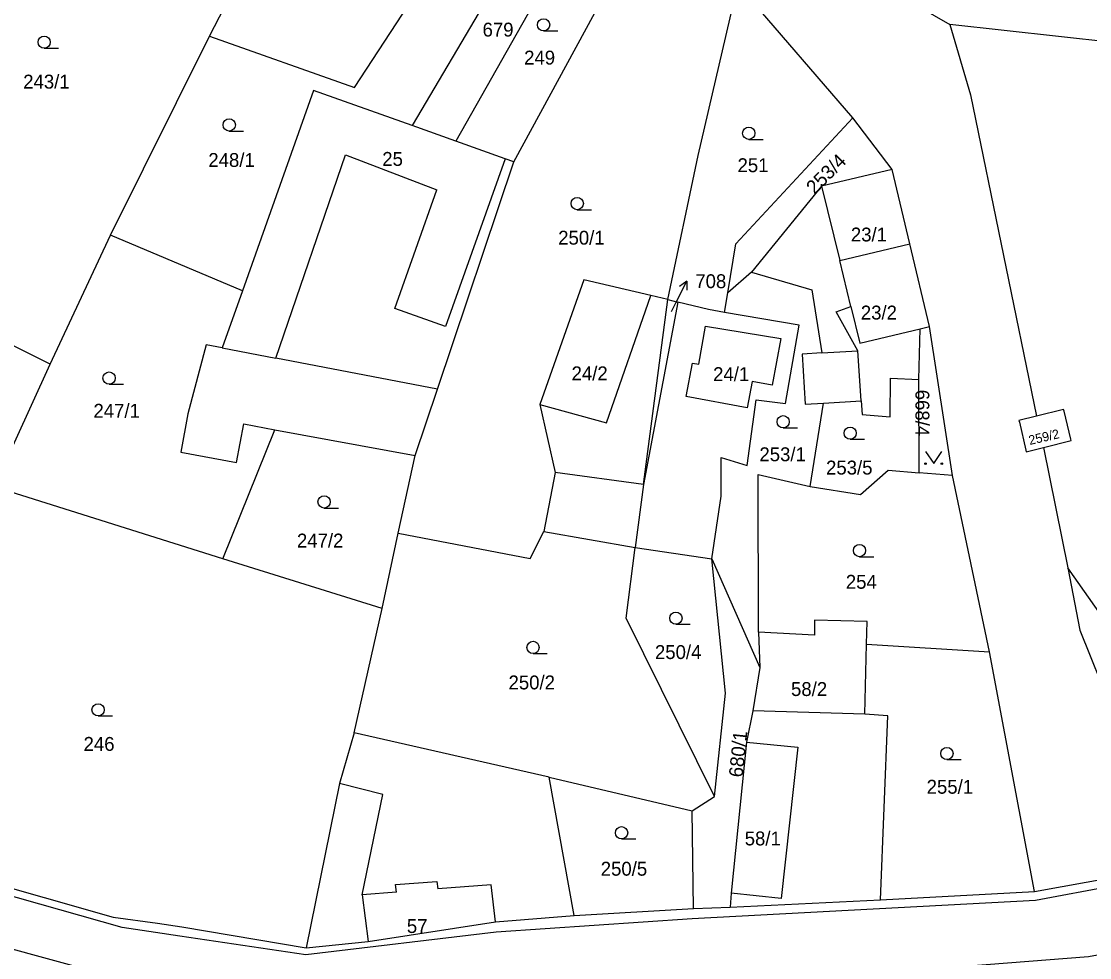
# Model space of a CAD drawing. Extents: x -747333 to -743907, y -1134120 to -1130051.
# Drawn here: x -746462.8 to -746332, y -1132327 to -1132212.3 of the extents above; entities that cross this region are included whole.
import ezdxf

# ---------------------------------------------------------------- set-up
doc = ezdxf.new("R2010")
doc.units = 0
for name, color, linetype in [('Hranice parcel', 7, 'Continuous'), ('Parcelní čísla', 7, 'Continuous'), ('Pop  PČ popisy', 7, 'Continuous'), ('Vnitřní kresba', 7, 'Continuous'), ('Značky kultur', 7, 'Continuous')]:
    doc.layers.add(name, color=color, linetype=linetype)

msp = doc.modelspace()

# ---------------------------------------------------------------- linework, layer by layer
at = {"layer": 'Hranice parcel'}
for p, q in [((-746385.31, -1132191.74), (-746349.14, -1132212.69)), ((-746439.77, -1132214.12), (-746430.73, -1132196.48)), ((-746398.19, -1132196.61), (-746414.98, -1132225.06)), ((-746394.06, -1132199.47), (-746409.61, -1132226.97)), ((-746402.53, -1132229.49), (-746387.86, -1132202.51)), ((-746451.89, -1132238.47), (-746439.77, -1132214.12)), ((-746356.19, -1132230.43), (-746361.01, -1132224.1)), ((-746409.61, -1132226.97), (-746414.98, -1132225.06)), ((-746354.02, -1132239.56), (-746356.19, -1132230.43)), ((-746459.31, -1132254.28), (-746451.89, -1132238.47)), ((-746435.76, -1132245.3), (-746451.89, -1132238.47)), ((-746351.62, -1132249.69), (-746354.02, -1132239.56)), ((-746459.31, -1132254.28), (-746488.24, -1132239.95)), ((-746373.4, -1132243.01), (-746376.31, -1132245.54)), ((-746386.66, -1132269.02), (-746383.65, -1132246.38)), ((-746383.65, -1132246.38), (-746382.45, -1132246.69)), ((-746376.71, -1132247.95), (-746376.31, -1132245.54)), ((-746382.45, -1132246.69), (-746386.66, -1132269.02)), ((-746367.58, -1132249.53), (-746376.71, -1132247.95)), ((-746369.24, -1132259.11), (-746367.58, -1132249.53)), ((-746348.82, -1132267.93), (-746351.62, -1132249.69)), ((-746466.16, -1132269.31), (-746459.31, -1132254.28)), ((-746352.9, -1132267.59), (-746352.94, -1132256.15)), ((-746366.22, -1132269.26), (-746364.59, -1132259.06)), ((-746364.59, -1132259.06), (-746360, -1132258.78)), ((-746435.59, -1132261.62), (-746431.77, -1132262.32)), ((-746438.16, -1132278.12), (-746431.77, -1132262.32)), ((-746431.77, -1132262.32), (-746414.59, -1132265.47)), ((-746337.67, -1132264.5), (-746334.69, -1132279.22)), ((-746416.68, -1132275.01), (-746414.59, -1132265.47)), ((-746348.82, -1132267.93), (-746352.9, -1132267.59)), ((-746344.28, -1132289.52), (-746348.82, -1132267.93)), ((-746438.16, -1132278.12), (-746466.16, -1132269.31)), ((-746386.66, -1132269.02), (-746387.66, -1132276.75)), ((-746418.66, -1132284.23), (-746416.68, -1132275.01)), ((-746398.85, -1132274.79), (-746387.66, -1132276.75)), ((-746387.66, -1132276.75), (-746378.28, -1132278.15)), ((-746418.66, -1132284.23), (-746438.16, -1132278.12)), ((-746378.28, -1132278.15), (-746372.39, -1132291.44)), ((-746422.09, -1132299.47), (-746418.66, -1132284.23)), ((-746372.56, -1132287.12), (-746372.39, -1132291.44)), ((-746359.56, -1132297.17), (-746359.35, -1132288.57)), ((-746359.35, -1132288.57), (-746344.28, -1132289.52)), ((-746338.75, -1132318.87), (-746344.28, -1132289.52)), ((-746372.39, -1132291.44), (-746373.25, -1132296.77)), ((-746359.56, -1132297.17), (-746373.25, -1132296.77)), ((-746398.2, -1132304.9), (-746422.09, -1132299.47)), ((-746398.2, -1132304.9), (-746380.7, -1132309.01)), ((-746395.13, -1132321.84), (-746398.2, -1132304.9)), ((-746380.7, -1132309.01), (-746377.93, -1132307.24)), ((-746380.5, -1132320.99), (-746380.7, -1132309.01)), ((-746338.75, -1132318.87), (-746321.59, -1132315.77)), ((-746357.62, -1132319.89), (-746338.75, -1132318.87)), ((-746395.13, -1132321.84), (-746380.5, -1132320.99)), ((-746380.5, -1132320.99), (-746376.02, -1132320.81)), ((-746376.02, -1132320.81), (-746357.62, -1132319.89))]:
    msp.add_line(p, q, dxfattribs=at)
for points in [[(-746439.77, -1132214.12), (-746422.02, -1132220.4), (-746413.23, -1132206.88), (-746403.66, -1132192.14)], [(-746383.65, -1132246.38), (-746379.95, -1132228.73), (-746375.2, -1132208.32)], [(-746361.01, -1132224.1), (-746374.1, -1132208.89), (-746375.2, -1132208.32)], [(-746308.1, -1132223.28), (-746309.97, -1132217.3), (-746329.17, -1132214.87), (-746349.14, -1132212.69)], [(-746349.14, -1132212.69), (-746346.6, -1132221.28), (-746338.5, -1132260.67)], [(-746414.98, -1132225.06), (-746427.06, -1132220.77), (-746435.76, -1132245.3)], [(-746376.31, -1132245.54), (-746375.33, -1132239.55), (-746361.01, -1132224.1)], [(-746402.53, -1132229.49), (-746403.57, -1132229.12), (-746409.61, -1132226.97)], [(-746414.59, -1132265.47), (-746411.87, -1132257.36), (-746402.53, -1132229.49)], [(-746356.19, -1132230.43), (-746364.83, -1132232.5), (-746373.4, -1132243.01)], [(-746361.26, -1132247.22), (-746362.62, -1132241.61), (-746354.02, -1132239.56)], [(-746373.4, -1132243.01), (-746366.05, -1132245.19), (-746364.79, -1132252.91), (-746367.22, -1132253.06)], [(-746383.65, -1132246.38), (-746385.74, -1132245.89), (-746393.93, -1132243.96), (-746399.35, -1132259.24), (-746397.47, -1132267.55), (-746398.85, -1132274.79)], [(-746435.76, -1132245.3), (-746438.24, -1132252.29), (-746440.19, -1132251.91), (-746442.43, -1132260.37), (-746443.3, -1132265.09)], [(-746376.71, -1132247.95), (-746378.69, -1132247.61), (-746382.45, -1132246.69)], [(-746360, -1132258.78), (-746360.38, -1132252.64), (-746363.05, -1132247.88), (-746361.26, -1132247.22)], [(-746352.94, -1132256.15), (-746352.78, -1132249.96), (-746351.62, -1132249.69)], [(-746367.22, -1132253.06), (-746366.84, -1132259.2), (-746364.59, -1132259.06)], [(-746360, -1132258.78), (-746359.86, -1132260.47), (-746356.42, -1132260.75), (-746356.38, -1132256.01), (-746352.94, -1132256.15)], [(-746378.28, -1132278.15), (-746377.13, -1132270.44), (-746377.15, -1132265.72), (-746373.96, -1132266.7), (-746372.85, -1132258.64), (-746369.24, -1132259.11)], [(-746338.5, -1132260.67), (-746340.67, -1132261.21), (-746340.62, -1132261.4), (-746339.84, -1132264.84), (-746339.8, -1132265.03), (-746337.67, -1132264.5)], [(-746337.67, -1132264.5), (-746334.26, -1132263.66), (-746334.31, -1132263.47), (-746335.15, -1132260.05), (-746335.2, -1132259.86), (-746338.5, -1132260.67)], [(-746443.3, -1132265.09), (-746436.46, -1132266.34), (-746435.59, -1132261.62)], [(-746366.22, -1132269.26), (-746360.07, -1132270.26), (-746356.7, -1132267.27), (-746352.9, -1132267.59)], [(-746372.56, -1132287.12), (-746372.62, -1132267.81), (-746366.22, -1132269.26)], [(-746416.68, -1132275.01), (-746400.51, -1132278.11), (-746398.85, -1132274.79)], [(-746377.93, -1132307.24), (-746388.78, -1132285.42), (-746387.66, -1132276.75)], [(-746377.93, -1132307.24), (-746376.62, -1132294.6), (-746378.28, -1132278.15)], [(-746301.77, -1132297.36), (-746306.9, -1132297.19), (-746324.77, -1132293.34), (-746334.69, -1132279.22)], [(-746334.69, -1132279.22), (-746333.21, -1132286.86), (-746321.59, -1132315.77)], [(-746359.35, -1132288.57), (-746359.26, -1132285.83), (-746365.72, -1132285.66), (-746365.72, -1132287.5), (-746372.56, -1132287.12)], [(-746373.25, -1132296.77), (-746374.02, -1132300.61), (-746375.92, -1132319.08), (-746376.02, -1132320.81)], [(-746357.62, -1132319.89), (-746356.71, -1132297.35), (-746359.56, -1132297.17)], [(-746422.09, -1132299.47), (-746423.86, -1132305.66), (-746427.94, -1132325.8)], [(-746485.44, -1132312.39), (-746451.58, -1132322.02), (-746446.14, -1132322.78), (-746443.16, -1132323.2), (-746427.94, -1132325.8)], [(-746427.94, -1132325.8), (-746420.34, -1132325.03), (-746404.78, -1132322.59), (-746395.13, -1132321.84)]]:
    msp.add_lwpolyline(points, dxfattribs=at)
at = {"layer": 'Pop  PČ popisy'}
for p, q in [((-746382.68, -1132246.79), (-746381.318, -1132244.116)), ((-746381.318, -1132244.116), (-746382.218, -1132244.781)), ((-746381.318, -1132244.116), (-746381.326, -1132245.236)), ((-746383.22, -1132247.84), (-746382.68, -1132246.79))]:
    msp.add_line(p, q, dxfattribs=at)
at = {"layer": 'Vnitřní kresba'}
for p, q in [((-746431.66, -1132253.55), (-746423.15, -1132228.66)), ((-746423.15, -1132228.66), (-746411.94, -1132232.94)), ((-746403.57, -1132229.12), (-746410.88, -1132249.69)), ((-746417.11, -1132247.47), (-746411.94, -1132232.94)), ((-746364.83, -1132232.5), (-746362.62, -1132241.61)), ((-746391.16, -1132261.46), (-746385.74, -1132245.89)), ((-746410.88, -1132249.69), (-746417.11, -1132247.47)), ((-746361.26, -1132247.22), (-746360.17, -1132251.72)), ((-746360.17, -1132251.72), (-746352.78, -1132249.96)), ((-746438.24, -1132252.29), (-746431.66, -1132253.55)), ((-746364.79, -1132252.91), (-746360.38, -1132252.64)), ((-746411.87, -1132257.36), (-746431.66, -1132253.55)), ((-746399.35, -1132259.24), (-746391.16, -1132261.46)), ((-746386.66, -1132269.02), (-746397.47, -1132267.55)), ((-746374.02, -1132300.61), (-746367.75, -1132301.19)), ((-746367.75, -1132301.19), (-746369.8, -1132319.75)), ((-746418.57, -1132307), (-746423.86, -1132305.66)), ((-746421.11, -1132319.3), (-746418.57, -1132307)), ((-746332.14, -1132326.83), (-746231.85, -1132308.88)), ((-746450.49, -1132323.31), (-746485.8, -1132313.24)), ((-746321.12, -1132316.7), (-746338.63, -1132320.01)), ((-746417, -1132318.01), (-746411.93, -1132317.65)), ((-746416.89, -1132318.97), (-746417, -1132318.01)), ((-746411.93, -1132317.65), (-746411.81, -1132318.58)), ((-746405.28, -1132318.08), (-746411.81, -1132318.58)), ((-746404.78, -1132322.59), (-746405.28, -1132318.08)), ((-746416.89, -1132318.97), (-746421.11, -1132319.3)), ((-746421.11, -1132319.3), (-746420.34, -1132325.03)), ((-746369.8, -1132319.75), (-746375.92, -1132319.08)), ((-746338.63, -1132320.01), (-746380.7, -1132322.22)), ((-746380.7, -1132322.22), (-746404.7, -1132323.87)), ((-746446.39, -1132323.91), (-746450.49, -1132323.31)), ((-746443.42, -1132324.35), (-746446.39, -1132323.91)), ((-746428.01, -1132326.63), (-746443.42, -1132324.35)), ((-746404.7, -1132323.87), (-746428.01, -1132326.63)), ((-746464.89, -1132325.65), (-746447.83, -1132330.31)), ((-746395.58, -1132331.79), (-746332.14, -1132326.83))]:
    msp.add_line(p, q, dxfattribs=at)
msp.add_lwpolyline([(-746379.07, -1132249.64), (-746369.84, -1132251.15), (-746370.87, -1132256.87), (-746373.34, -1132256.42), (-746373.93, -1132259.62), (-746381.42, -1132258.26), (-746380.65, -1132254.15), (-746379.86, -1132254.3), (-746379.07, -1132249.64)], dxfattribs=at)
at = {"layer": 'Značky kultur'}
for p, q in [((-746398.873, -1132213.47), (-746397.123, -1132213.47)), ((-746460.033, -1132215.6), (-746458.283, -1132215.6)), ((-746437.373, -1132225.74), (-746435.623, -1132225.74)), ((-746373.753, -1132226.76), (-746372.003, -1132226.76)), ((-746394.753, -1132235.37), (-746393.003, -1132235.37)), ((-746452.083, -1132256.74), (-746450.333, -1132256.74)), ((-746369.543, -1132262.09), (-746367.793, -1132262.09)), ((-746361.333, -1132263.49), (-746359.583, -1132263.49)), ((-746425.753, -1132271.91), (-746424.003, -1132271.91)), ((-746360.193, -1132277.88), (-746358.443, -1132277.88)), ((-746382.673, -1132286.15), (-746380.923, -1132286.15)), ((-746400.173, -1132289.74), (-746398.423, -1132289.74)), ((-746453.433, -1132297.38), (-746451.683, -1132297.38)), ((-746349.483, -1132302.73), (-746347.733, -1132302.73)), ((-746389.323, -1132312.44), (-746387.573, -1132312.44))]:
    msp.add_line(p, q, dxfattribs=at)
msp.add_lwpolyline([(-746352.11, -1132264.969), (-746351.11, -1132266.47), (-746350.11, -1132264.969)], dxfattribs=at)
for centre, radius in [((-746398.873, -1132212.72), 0.75), ((-746460.033, -1132214.85), 0.75), ((-746437.373, -1132224.99), 0.75), ((-746373.753, -1132226.01), 0.75), ((-746394.753, -1132234.62), 0.75), ((-746452.083, -1132255.99), 0.75), ((-746369.543, -1132261.34), 0.75), ((-746361.333, -1132262.74), 0.75), ((-746352.11, -1132266.469), 0.1), ((-746350.11, -1132266.469), 0.1), ((-746425.753, -1132271.16), 0.75), ((-746360.193, -1132277.13), 0.75), ((-746382.673, -1132285.4), 0.75), ((-746400.173, -1132288.99), 0.75), ((-746453.433, -1132296.63), 0.75), ((-746349.483, -1132301.98), 0.75), ((-746389.323, -1132311.69), 0.75)]:
    msp.add_circle(centre, radius, dxfattribs=at)

# ---------------------------------------------------------------- texts
at = {"layer": 'Parcelní čísla'}
for s, p in [('679', (-746406.35, -1132214.16)), ('249', (-746401.26, -1132217.59)), ('243/1', (-746462.6, -1132220.53)), ('248/1', (-746439.93, -1132230.13)), ('25', (-746418.63, -1132230)), ('251', (-746375.13, -1132230.77)), ('250/1', (-746397.09, -1132239.65)), ('23/1', (-746361.25, -1132239.26)), ('708', (-746380.3, -1132244.98)), ('23/2', (-746360.03, -1132248.82)), ('24/2', (-746395.451, -1132256.27)), ('24/1', (-746378.121, -1132256.36)), ('247/1', (-746454, -1132260.85)), ('253/1', (-746372.45, -1132266.18)), ('253/5', (-746364.29, -1132267.81)), ('247/2', (-746429.08, -1132276.75)), ('254', (-746361.87, -1132281.8)), ('250/4', (-746385.24, -1132290.41)), ('250/2', (-746403.17, -1132294.13)), ('58/2', (-746368.58, -1132294.94)), ('246', (-746455.21, -1132301.66)), ('255/1', (-746351.97, -1132306.91)), ('58/1', (-746374.25, -1132313.24)), ('250/5', (-746391.88, -1132316.95)), ('57', (-746415.62, -1132323.97))]:
    msp.add_text(s, height=1.7, dxfattribs=at).set_placement(p)
for s, height, rotation, p in [('253/4', 1.7, 45, (-746365.698, -1132233.591)), ('668/4', 1.7, 270, (-746353.34, -1132257.42)), ('259/2', 1.14, 13, (-746339.341, -1132264.195)), ('680/1', 1.7, 84, (-746374.514, -1132304.958))]:
    msp.add_text(s, height=height, rotation=rotation, dxfattribs=at).set_placement(p)

doc.saveas('drawing.dxf')
